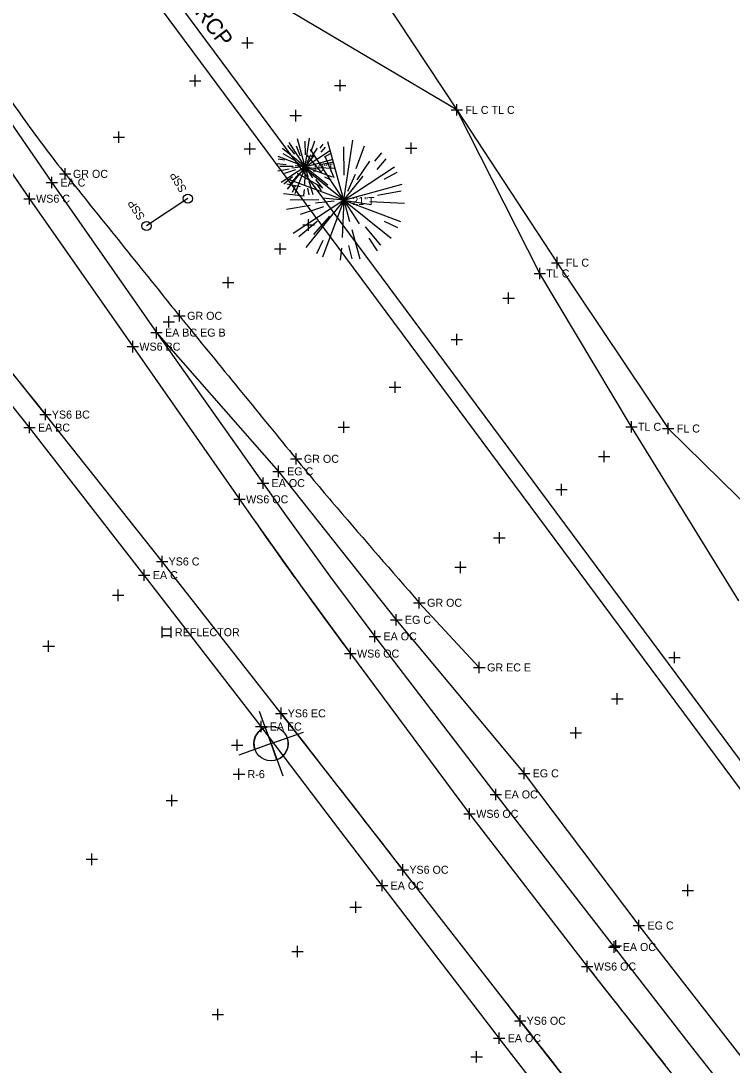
# Model space of a CAD drawing. Extents: x 1324236 to 1326110, y 459090 to 460782.
# Drawn here: x 1325582.8 to 1325707.2, y 459875.9 to 460058.5 of the extents above; entities that cross this region are included whole.
import ezdxf

# ---------------------------------------------------------------- set-up
doc = ezdxf.new("R2010")
doc.units = 0
for name, color, linetype in [('DR_X_Ditch', 7, 'Continuous'), ('DT_X_Contour_Minor', 7, 'Continuous'), ('DT_X_Terrain_Ground_Line', 7, 'Continuous'), ('DV_X_Property_Line', 7, 'Continuous'), ('GT_Project_Soil_Boring', 7, 'Continuous'), ('LT_X_Poles', 7, 'Continuous'), ('PM_X_CL_Double_Solid', 7, 'Continuous'), ('PM_X_Edge_Line', 7, 'Continuous'), ('PM_X_Parking_Lot_Stall', 7, 'Continuous'), ('PV_X_Shoulder', 7, 'Continuous'), ('PV_X_Shoulder_Aggregate', 7, 'Continuous'), ('RD_X_GR_Lt', 7, 'Continuous'), ('RW_X_CL', 7, 'Continuous'), ('RW_X_Esmt_SH', 7, 'Continuous'), ('UT_X_Telecom', 7, 'Continuous'), ('VG_X_Cells', 7, 'Continuous'), ('VG_X_Flower_Bed', 7, 'Continuous')]:
    doc.layers.add(name, color=color, linetype=linetype)

msp = doc.modelspace()

# ---------------------------------------------------------------- linework, layer by layer
at = {"layer": 'DR_X_Ditch'}
for points in [[(1325565.79, 460054.08), (1325584.28, 460027.39), (1325602.35, 460001.52), (1325623.02, 459971.97), (1325631.64, 459959.84), (1325640.43, 459947.84), (1325640.43, 459947.84), (1325661.29, 459919.82), (1325681.88, 459893.12), (1325695.48, 459875.88), (1325695.48, 459875.88), (1325702.4, 459867.23)], [(1325679.02, 459872.3), (1325670.15, 459883.63), (1325670.15, 459883.63), (1325667.84, 459886.61), (1325667.84, 459886.61), (1325649.62, 459910.04), (1325642.42, 459919.3), (1325642.42, 459919.3), (1325628.35, 459937.39), (1325628.35, 459937.39), (1325607.49, 459963.95), (1325587.07, 459989.64), (1325574.08, 460005.86)]]:
    msp.add_lwpolyline(points, dxfattribs=at)
at = {"layer": 'DT_X_Contour_Minor'}
msp.add_line((1325611.99, 460027.41), (1325604.76, 460022.62), dxfattribs=at)
for centre in [(1325611.99, 460027.41), (1325604.76, 460022.62)]:
    msp.add_circle(centre, 0.8, dxfattribs=at)
at = {"layer": 'DT_X_Terrain_Ground_Line'}
for p, q in [((1325607.43, 459952.59), (1325607.43, 459950.59)), ((1325607.43, 459952.18), (1325609.03, 459952.18)), ((1325609.03, 459952.59), (1325609.03, 459950.59)), ((1325607.43, 459950.98), (1325609.03, 459950.98))]:
    msp.add_line(p, q, dxfattribs=at)
at = {"layer": 'DV_X_Property_Line'}
for p, q in [((1325587.2, 460030.22), (1325589.2, 460030.22)), ((1325588.2, 460029.22), (1325588.2, 460031.22)), ((1325606.5, 460002.97), (1325606.5, 460004.97)), ((1325605.5, 460003.97), (1325607.5, 460003.97)), ((1325584.27, 459986.36), (1325584.27, 459988.36)), ((1325583.27, 459987.36), (1325585.27, 459987.36)), ((1325627.86, 459978.71), (1325627.86, 459980.71)), ((1325625.15, 459976.66), (1325625.15, 459978.66)), ((1325626.86, 459979.71), (1325628.86, 459979.71)), ((1325624.15, 459977.66), (1325626.15, 459977.66)), ((1325604.37, 459960.56), (1325604.37, 459962.56)), ((1325603.37, 459961.56), (1325605.37, 459961.56)), ((1325647.47, 459953.75), (1325649.47, 459953.75)), ((1325648.47, 459952.75), (1325648.47, 459954.75)), ((1325644.73, 459949.85), (1325644.73, 459951.85)), ((1325643.73, 459950.85), (1325645.73, 459950.85)), ((1325623.82, 459935.09), (1325625.82, 459935.09)), ((1325624.82, 459934.09), (1325624.82, 459936.09)), ((1325670.82, 459925.9), (1325670.82, 459927.9)), ((1325669.82, 459926.9), (1325671.82, 459926.9)), ((1325665.9, 459922.21), (1325665.9, 459924.21)), ((1325664.9, 459923.21), (1325666.9, 459923.21)), ((1325645.97, 459906.28), (1325645.97, 459908.28)), ((1325644.97, 459907.28), (1325646.97, 459907.28)), ((1325689.92, 459900.29), (1325691.92, 459900.29)), ((1325690.92, 459899.29), (1325690.92, 459901.29)), ((1325685.59, 459896.53), (1325687.59, 459896.53)), ((1325686.59, 459895.53), (1325686.59, 459897.53)), ((1325665.46, 459880.58), (1325667.46, 459880.58)), ((1325666.46, 459879.58), (1325666.46, 459881.58))]:
    msp.add_line(p, q, dxfattribs=at)
at = {"layer": 'GT_Project_Soil_Boring'}
for p, q in [((1325626.56, 459932.1), (1325624.54, 459937.74)), ((1325625.55, 459934.92), (1325626.56, 459932.1)), ((1325626.56, 459932.1), (1325632.21, 459934.12)), ((1325626.56, 459932.1), (1325629.39, 459933.11)), ((1325626.56, 459932.1), (1325620.92, 459930.07)), ((1325626.56, 459932.1), (1325623.74, 459931.08)), ((1325626.56, 459932.1), (1325628.59, 459926.45)), ((1325627.58, 459929.27), (1325626.56, 459932.1))]:
    msp.add_line(p, q, dxfattribs=at)
msp.add_circle((1325626.56, 459932.1), 3, dxfattribs=at)
for start, end in [(109.7344, 199.7344), (289.7344, 19.7344)]:
    msp.add_arc((1325626.56, 459932.1), 3, start, end, dxfattribs=at)
at = {"layer": 'LT_X_Poles'}
for points in [[(1325565.79, 460054.08), (1325584.28, 460027.39), (1325602.35, 460001.52), (1325623.02, 459971.97), (1325631.64, 459959.84), (1325640.43, 459947.84), (1325640.43, 459947.84), (1325661.29, 459919.82), (1325681.88, 459893.12), (1325695.48, 459875.88), (1325695.48, 459875.88), (1325702.4, 459867.23)], [(1325679.02, 459872.3), (1325670.15, 459883.63), (1325670.15, 459883.63), (1325667.84, 459886.61), (1325667.84, 459886.61), (1325649.62, 459910.04), (1325642.42, 459919.3), (1325642.42, 459919.3), (1325628.35, 459937.39), (1325628.35, 459937.39), (1325607.49, 459963.95), (1325587.07, 459989.64), (1325574.08, 460005.86)]]:
    msp.add_lwpolyline(points, dxfattribs=at)
at = {"layer": 'PM_X_CL_Double_Solid'}
for p, q in [((1325641.47, 460069.54), (1325659.05, 460042.91)), ((1325659.05, 460042.91), (1325676.64, 460016.2)), ((1325676.64, 460016.2), (1325696.04, 459987.2)), ((1325696.04, 459987.2), (1325717.94, 459965.66))]:
    msp.add_line(p, q, dxfattribs=at)
at = {"layer": 'PM_X_Edge_Line'}
for p, q in [((1325565.79, 460054.08), (1325584.28, 460027.39)), ((1325584.28, 460027.39), (1325602.35, 460001.52)), ((1325602.35, 460001.52), (1325623.02, 459971.97)), ((1325607.49, 459963.95), (1325587.07, 459989.64)), ((1325628.35, 459937.39), (1325607.49, 459963.95)), ((1325640.43, 459947.84), (1325661.29, 459919.82)), ((1325661.29, 459919.82), (1325681.88, 459893.12)), ((1325667.84, 459886.61), (1325649.62, 459910.04))]:
    msp.add_line(p, q, dxfattribs=at)
for centre, radius, start, end in [((1330829.75, 464201.07), 6724.72, 218.597815, 218.774832), ((1326445.02, 460546.86), 1003.08, 214.96849, 216.66809), ((1190525.34, 354830.5), 171173.26, 37.8743855, 37.8820568), ((1290250.2, 432392.6), 44836.69, 37.859407, 37.874396), ((1329279.86, 462717.84), 4574.33, 218.13488, 218.41001), ((1352985.7, 481121.32), 34600.27, 217.858626, 217.864872), ((1327530.99, 461330.42), 2357.1, 217.86487, 218.21448)]:
    msp.add_arc(centre, radius, start, end, dxfattribs=at)
at = {"layer": 'PM_X_Parking_Lot_Stall'}
msp.add_line((1325652.49, 459956.73), (1325662.99, 459945.42), dxfattribs=at)
for centre, radius, start, end in [((1326187.06, 460471.05), 741.08, 213.87094, 215.52925), ((1325739.19, 460151.24), 190.74, 215.5293, 218.7983), ((1381071.16, 504636.58), 71187.73, 218.7982931, 218.8220512), ((1325957.55, 460289.16), 447.33, 218.822, 219.1218), ((1326448.24, 460688.24), 1079.82, 219.12176, 219.24476), ((1465466.36, 574249.6), 180585.31, 219.2447578, 219.2542687), ((1326006.34, 460288.66), 484.8, 219.2543, 220.5772), ((1327053.31, 461185.3), 1863.24, 220.57723, 221.25206)]:
    msp.add_arc(centre, radius, start, end, dxfattribs=at)
at = {"layer": 'PV_X_Shoulder'}
for points in [[(1325569.83, 460056.87), (1325588.2, 460030.22), (1325606.5, 460003.97), (1325629.33, 459971.76), (1325636.94, 459961.23), (1325644.73, 459950.85), (1325644.73, 459950.85), (1325665.9, 459923.21), (1325686.59, 459896.53), (1325700.04, 459879.13), (1325700.04, 459879.13), (1325707.06, 459870.28)], [(1325677.99, 459865.75), (1325666.46, 459880.58), (1325666.46, 459880.58), (1325665.93, 459881.27), (1325665.93, 459881.27), (1325645.97, 459907.28), (1325645.97, 459907.28), (1325638.76, 459916.71), (1325638.76, 459916.71), (1325624.82, 459935.09), (1325624.82, 459935.09), (1325604.37, 459961.56), (1325584.27, 459987.36), (1325571.22, 460003.75)]]:
    msp.add_lwpolyline(points, dxfattribs=at)
at = {"layer": 'PV_X_Shoulder_Aggregate'}
msp.add_lwpolyline([(1325606.5, 460003.97), (1325627.86, 459979.71), (1325648.47, 459953.75), (1325670.82, 459926.9), (1325690.92, 459900.29), (1325711.62, 459873.72), (1325733.33, 459849.01), (1325756.75, 459825.62), (1325779.78, 459800.49), (1325802.43, 459775.88), (1325825.37, 459750.4), (1325848.07, 459724.61), (1325869.88, 459700.51), (1325892.16, 459676.27), (1325913.97, 459651.72)], dxfattribs=at)
at = {"layer": 'RD_X_GR_Lt'}
for p, q in [((1325659.05, 460042.91), (1325630.22, 460059.93)), ((1325673.57, 460014.31), (1325659.05, 460042.91)), ((1325689.63, 459987.5), (1325673.57, 460014.31)), ((1325708.41, 459957.08), (1325689.63, 459987.5))]:
    msp.add_line(p, q, dxfattribs=at)
at = {"layer": 'RW_X_CL'}
for p, q in [((1325622.44, 460053.63), (1325622.44, 460055.63)), ((1325621.44, 460054.63), (1325623.44, 460054.63)), ((1325612.27, 460048.02), (1325614.27, 460048.02)), ((1325613.27, 460047.02), (1325613.27, 460049.02)), ((1325638.66, 460046.2), (1325638.66, 460048.2)), ((1325637.66, 460047.2), (1325639.66, 460047.2)), ((1325630.86, 460040.91), (1325630.86, 460042.91)), ((1325629.86, 460041.91), (1325631.86, 460041.91)), ((1325599.93, 460037.13), (1325599.93, 460039.13)), ((1325598.93, 460038.13), (1325600.93, 460038.13)), ((1325622.83, 460035.13), (1325622.83, 460037.13)), ((1325651.05, 460035.24), (1325651.05, 460037.24)), ((1325621.83, 460036.13), (1325623.83, 460036.13)), ((1325650.05, 460036.24), (1325652.05, 460036.24)), ((1325584.28, 460026.39), (1325584.28, 460028.39)), ((1325583.28, 460027.39), (1325585.28, 460027.39)), ((1325632.13, 460022.79), (1325634.13, 460022.79)), ((1325633.13, 460021.79), (1325633.13, 460023.79)), ((1325628.17, 460017.61), (1325628.17, 460019.61)), ((1325627.17, 460018.61), (1325629.17, 460018.61)), ((1325619.05, 460011.73), (1325619.05, 460013.73)), ((1325618.05, 460012.73), (1325620.05, 460012.73)), ((1325667.12, 460010.01), (1325669.12, 460010.01)), ((1325668.12, 460009.01), (1325668.12, 460011.01)), ((1325608.67, 460004.86), (1325608.67, 460006.86)), ((1325607.67, 460005.86), (1325609.67, 460005.86)), ((1325602.35, 460000.52), (1325602.35, 460002.52)), ((1325658.06, 460002.77), (1325660.06, 460002.77)), ((1325659.06, 460001.77), (1325659.06, 460003.77)), ((1325601.35, 460001.52), (1325603.35, 460001.52)), ((1325648.24, 459993.42), (1325648.24, 459995.42)), ((1325647.24, 459994.42), (1325649.24, 459994.42)), ((1325586.07, 459989.64), (1325588.07, 459989.64)), ((1325587.07, 459988.64), (1325587.07, 459990.64)), ((1325639.29, 459986.44), (1325639.29, 459988.44)), ((1325638.29, 459987.44), (1325640.29, 459987.44)), ((1325683.82, 459982.31), (1325685.82, 459982.31)), ((1325684.82, 459981.31), (1325684.82, 459983.31)), ((1325677.38, 459975.51), (1325677.38, 459977.51)), ((1325621.03, 459973.82), (1325621.03, 459975.82)), ((1325676.38, 459976.51), (1325678.38, 459976.51)), ((1325620.03, 459974.82), (1325622.03, 459974.82)), ((1325665.5, 459968.1), (1325667.5, 459968.1)), ((1325666.5, 459967.1), (1325666.5, 459969.1)), ((1325607.49, 459962.95), (1325607.49, 459964.95)), ((1325606.49, 459963.95), (1325608.49, 459963.95)), ((1325658.71, 459962.93), (1325660.71, 459962.93)), ((1325659.71, 459961.93), (1325659.71, 459963.93)), ((1325599.81, 459957.03), (1325599.81, 459959.03)), ((1325598.81, 459958.03), (1325600.81, 459958.03)), ((1325587.64, 459948.13), (1325587.64, 459950.13)), ((1325586.64, 459949.13), (1325588.64, 459949.13)), ((1325639.43, 459947.84), (1325641.43, 459947.84)), ((1325640.43, 459946.84), (1325640.43, 459948.84)), ((1325697.14, 459946.15), (1325697.14, 459948.15)), ((1325696.14, 459947.15), (1325698.14, 459947.15)), ((1325687.14, 459938.91), (1325687.14, 459940.91)), ((1325686.14, 459939.91), (1325688.14, 459939.91)), ((1325627.35, 459937.39), (1325629.35, 459937.39)), ((1325628.35, 459936.39), (1325628.35, 459938.39)), ((1325679.86, 459932.97), (1325679.86, 459934.97)), ((1325678.86, 459933.97), (1325680.86, 459933.97)), ((1325619.64, 459931.82), (1325621.64, 459931.82)), ((1325620.64, 459930.82), (1325620.64, 459932.82)), ((1325620.94, 459925.76), (1325620.94, 459927.76)), ((1325619.94, 459926.76), (1325621.94, 459926.76)), ((1325608.2, 459922.15), (1325610.2, 459922.15)), ((1325609.2, 459921.15), (1325609.2, 459923.15)), ((1325661.29, 459918.82), (1325661.29, 459920.82)), ((1325660.29, 459919.82), (1325662.29, 459919.82)), ((1325594.18, 459911.87), (1325596.18, 459911.87)), ((1325595.18, 459910.87), (1325595.18, 459912.87)), ((1325648.62, 459910.04), (1325650.62, 459910.04)), ((1325649.62, 459909.04), (1325649.62, 459911.04)), ((1325699.46, 459905.44), (1325699.46, 459907.44)), ((1325698.46, 459906.44), (1325700.46, 459906.44)), ((1325641.36, 459902.5), (1325641.36, 459904.5)), ((1325640.36, 459903.5), (1325642.36, 459903.5)), ((1325631.16, 459894.75), (1325631.16, 459896.75)), ((1325685.85, 459896.74), (1325687.85, 459896.74)), ((1325686.85, 459895.74), (1325686.85, 459897.74)), ((1325630.16, 459895.75), (1325632.16, 459895.75)), ((1325680.88, 459893.12), (1325682.88, 459893.12)), ((1325681.88, 459892.12), (1325681.88, 459894.12)), ((1325617.22, 459883.71), (1325617.22, 459885.71)), ((1325616.22, 459884.71), (1325618.22, 459884.71)), ((1325670.15, 459882.63), (1325670.15, 459884.63)), ((1325669.15, 459883.63), (1325671.15, 459883.63)), ((1325662.52, 459876.32), (1325662.52, 459878.32)), ((1325661.52, 459877.32), (1325663.52, 459877.32))]:
    msp.add_line(p, q, dxfattribs=at)
at = {"layer": 'RW_X_Esmt_SH'}
for p, q in [((1325658.05, 460042.91), (1325660.05, 460042.91)), ((1325659.05, 460041.91), (1325659.05, 460043.91)), ((1325589.54, 460031.73), (1325591.54, 460031.73)), ((1325590.54, 460030.73), (1325590.54, 460032.73)), ((1325676.64, 460015.2), (1325676.64, 460017.2)), ((1325673.57, 460013.31), (1325673.57, 460015.31)), ((1325675.64, 460016.2), (1325677.64, 460016.2)), ((1325672.57, 460014.31), (1325674.57, 460014.31)), ((1325610.51, 460005.91), (1325610.51, 460007.91)), ((1325609.51, 460006.91), (1325611.51, 460006.91)), ((1325689.63, 459986.5), (1325689.63, 459988.5)), ((1325696.04, 459986.2), (1325696.04, 459988.2)), ((1325688.63, 459987.5), (1325690.63, 459987.5)), ((1325695.04, 459987.2), (1325697.04, 459987.2)), ((1325630.94, 459980.9), (1325630.94, 459982.9)), ((1325629.94, 459981.9), (1325631.94, 459981.9)), ((1325651.49, 459956.73), (1325653.49, 459956.73)), ((1325652.49, 459955.73), (1325652.49, 459957.73)), ((1325662.99, 459944.42), (1325662.99, 459946.42)), ((1325661.99, 459945.42), (1325663.99, 459945.42))]:
    msp.add_line(p, q, dxfattribs=at)
at = {"layer": 'VG_X_Cells'}
for p, q in [((1325632.52, 460032.98), (1325629.75, 460037.2)), ((1325632.52, 460032.98), (1325631.19, 460037.85)), ((1325632.52, 460032.98), (1325633.29, 460037.97)), ((1325632.55, 460035.06), (1325632.53, 460037.43)), ((1325633.55, 460035.63), (1325634.24, 460037.49)), ((1325633.55, 460035.63), (1325634.24, 460037.49)), ((1325639.27, 460027.12), (1325636.47, 460037.36)), ((1325639.27, 460027.12), (1325640.89, 460037.62)), ((1325632.52, 460032.98), (1325628.58, 460036.14)), ((1325630.74, 460035.19), (1325629.47, 460036.72)), ((1325631.73, 460034.84), (1325631, 460036.56)), ((1325632.52, 460032.98), (1325636.75, 460035.75)), ((1325639.27, 460027.12), (1325633.44, 460036)), ((1325633.65, 460034.66), (1325634.68, 460036.22)), ((1325635.12, 460036.22), (1325635.68, 460036.92)), ((1325635.3, 460035.54), (1325636.05, 460036.42)), ((1325635.88, 460034.73), (1325636.96, 460035.32)), ((1325639.34, 460031.5), (1325639.29, 460036.47)), ((1325641.44, 460032.69), (1325642.88, 460036.61)), ((1325641.44, 460032.69), (1325642.88, 460036.61)), ((1325644.72, 460033.93), (1325645.91, 460035.41)), ((1325629.22, 460033.32), (1325627.49, 460033.51)), ((1325628.91, 460034.1), (1325627.77, 460034.31)), ((1325632.52, 460032.98), (1325627.79, 460034.76)), ((1325630.73, 460034.05), (1325628.67, 460035.21)), ((1325639.27, 460027.12), (1325630.99, 460033.76)), ((1325632.52, 460032.98), (1325634.13, 460034.98)), ((1325632.52, 460032.98), (1325637.4, 460034.31)), ((1325632.86, 460033.72), (1325633.49, 460035.14)), ((1325635.53, 460031.78), (1325632.86, 460034.99)), ((1325635.33, 460033.41), (1325637.29, 460033.75)), ((1325637.61, 460031.04), (1325636.08, 460034.65)), ((1325641.63, 460030.66), (1325643.81, 460033.93)), ((1325645.1, 460032.51), (1325646.68, 460034.36)), ((1325629.71, 460032.54), (1325627.75, 460032.2)), ((1325630.44, 460033.01), (1325628.07, 460032.99)), ((1325632.52, 460032.98), (1325628.3, 460030.2)), ((1325630.84, 460032.42), (1325628.9, 460031.77)), ((1325632.52, 460032.98), (1325629.36, 460029.03)), ((1325631.34, 460031.65), (1325629.99, 460030.12)), ((1325631.71, 460032.9), (1325630.16, 460032.73)), ((1325632.52, 460032.98), (1325630.74, 460028.25)), ((1325632.52, 460032.98), (1325630.76, 460033.16)), ((1325635.52, 460029.37), (1325631.19, 460031.82)), ((1325632.52, 460032.98), (1325632.38, 460029.87)), ((1325632.52, 460032.98), (1325633.01, 460031.19)), ((1325632.52, 460032.98), (1325633.81, 460031.01)), ((1325632.52, 460032.98), (1325636.47, 460029.82)), ((1325632.52, 460032.98), (1325637.25, 460031.19)), ((1325632.52, 460032.98), (1325634.81, 460032.63)), ((1325634.71, 460032.87), (1325637.57, 460032.74)), ((1325639.27, 460027.12), (1325648.15, 460032.96)), ((1325639.98, 460028.68), (1325641.3, 460031.68)), ((1325646.33, 460030.8), (1325648.59, 460032.05)), ((1325630.31, 460031.2), (1325628.78, 460029.92)), ((1325631.7, 460029.48), (1325629.3, 460029.92)), ((1325639.27, 460027.12), (1325629.34, 460030.87)), ((1325633.19, 460030.54), (1325633.86, 460028.1)), ((1325634.3, 460030.76), (1325635.58, 460029.23)), ((1325634.61, 460029.8), (1325635.3, 460028.75)), ((1325635.89, 460031.24), (1325637, 460030.7)), ((1325639.27, 460027.12), (1325642.64, 460031.33)), ((1325639.27, 460027.12), (1325649.51, 460029.93)), ((1325632.34, 460027.86), (1325628.72, 460028.24)), ((1325630.78, 460029.61), (1325630.25, 460028.5)), ((1325632.33, 460028.97), (1325632.22, 460027.97)), ((1325632.93, 460029.22), (1325633.18, 460028.09)), ((1325645.18, 460028.03), (1325649.29, 460028.75)), ((1325633.37, 460026.21), (1325629.26, 460025.5)), ((1325634.9, 460027.19), (1325629.92, 460027.14)), ((1325639.27, 460027.12), (1325630.4, 460021.29)), ((1325639.27, 460027.12), (1325632.64, 460018.84)), ((1325637.58, 460026.96), (1325634.32, 460026.6)), ((1325639.27, 460027.12), (1325635.53, 460017.19)), ((1325639.27, 460027.12), (1325635.57, 460027.51)), ((1325639.27, 460027.12), (1325638.97, 460020.6)), ((1325639.27, 460027.12), (1325640.3, 460023.38)), ((1325639.27, 460027.12), (1325641.99, 460023)), ((1325639.27, 460027.12), (1325647.56, 460020.49)), ((1325639.27, 460027.12), (1325649.21, 460023.38)), ((1325639.27, 460027.12), (1325644.07, 460026.4)), ((1325643.86, 460026.91), (1325649.88, 460026.63)), ((1325635.73, 460025.95), (1325631.66, 460024.6)), ((1325636.79, 460024.33), (1325633.95, 460021.13)), ((1325634.62, 460023.38), (1325631.41, 460020.71)), ((1325643.01, 460022.47), (1325645.69, 460019.26)), ((1325646.35, 460023.47), (1325648.67, 460022.35)), ((1325640.68, 460022.01), (1325642.08, 460016.88)), ((1325635.62, 460020.05), (1325634.5, 460017.73)), ((1325640.12, 460019.23), (1325640.66, 460016.86)), ((1325643.65, 460020.46), (1325645.11, 460018.25)), ((1325638.86, 460018.71), (1325638.63, 460016.62))]:
    msp.add_line(p, q, dxfattribs=at)
at = {"layer": 'VG_X_Flower_Bed'}
for p, q in [((1325793.64, 459814.67), (1325591.57, 460086.9)), ((1325791.23, 459812.88), (1325589.16, 460085.11))]:
    msp.add_line(p, q, dxfattribs=at)

# ---------------------------------------------------------------- texts
at = {"layer": 'DT_X_Contour_Minor'}
for rotation, p in [(120.5377, (1325611.86, 460029.01)), (122.8185, (1325604.56, 460024.22))]:
    msp.add_text('SSP', height=1.4, rotation=rotation, dxfattribs=at).set_placement(p)
at = {"layer": 'DV_X_Property_Line'}
for s, p in [('EA C', (1325589.7, 460029.52)), ('EA BC EG B', (1325608, 460003.27)), ('EA BC', (1325585.77, 459986.66)), ('EG C', (1325629.36, 459979.01)), ('EA OC', (1325626.65, 459976.96)), ('EA C', (1325605.87, 459960.86)), ('EG C', (1325649.97, 459953.05)), ('EA OC', (1325646.23, 459950.15)), ('EA EC', (1325626.32, 459934.39)), ('EG C', (1325672.32, 459926.2)), ('EA OC', (1325667.4, 459922.51)), ('EA OC', (1325647.47, 459906.58)), ('EG C', (1325692.42, 459899.59)), ('EA OC', (1325688.09, 459895.83)), ('EA OC', (1325667.96, 459879.88))]:
    msp.add_text(s, height=1.4, dxfattribs=at).set_placement(p)
at = {"layer": 'RW_X_CL'}
for s, p in [('WS6 C', (1325585.45, 460026.69)), ('WS6 BC', (1325603.52, 460000.82)), ('YS6 BC', (1325588.19, 459988.94)), ('WS6 OC', (1325622.19, 459974.12)), ('YS6 C', (1325608.62, 459963.25)), ('WS6 OC', (1325641.6, 459947.14)), ('YS6 EC', (1325629.47, 459936.69)), ('R-6', (1325622.44, 459926.06)), ('WS6 OC', (1325662.46, 459919.12)), ('YS6 OC', (1325650.75, 459909.34)), ('WS6 OC', (1325683.04, 459892.42)), ('YS6 OC', (1325671.28, 459882.93))]:
    msp.add_text(s, height=1.4, dxfattribs=at).set_placement(p)
at = {"layer": 'RW_X_Esmt_SH'}
for s, p in [('FL C TL C', (1325660.55, 460042.21)), ('GR OC', (1325591.89, 460031.03)), ('FL C', (1325678.14, 460015.5)), ('TL C', (1325674.7, 460013.61)), ('GR OC', (1325611.87, 460006.21)), ('TL C', (1325690.76, 459986.8)), ('FL C', (1325697.54, 459986.5)), ('GR OC', (1325632.3, 459981.2)), ('GR OC', (1325653.85, 459956.03)), ('REFLECTOR', (1325609.73, 459950.88)), ('GR EC E', (1325664.35, 459944.72))]:
    msp.add_text(s, height=1.4, dxfattribs=at).set_placement(p)
at = {"layer": 'UT_X_Telecom'}
msp.add_text('EX. 36" RCP', height=2.8, rotation=306.9189, dxfattribs=at).set_placement((1325604.93, 460070.85))
at = {"layer": 'VG_X_Cells'}
for s, p in [('10"T', (1325633.72, 460032.14)), ('21"T', (1325640.77, 460026.29))]:
    msp.add_text(s, height=1.4, dxfattribs=at).set_placement(p)

doc.saveas('drawing.dxf')
